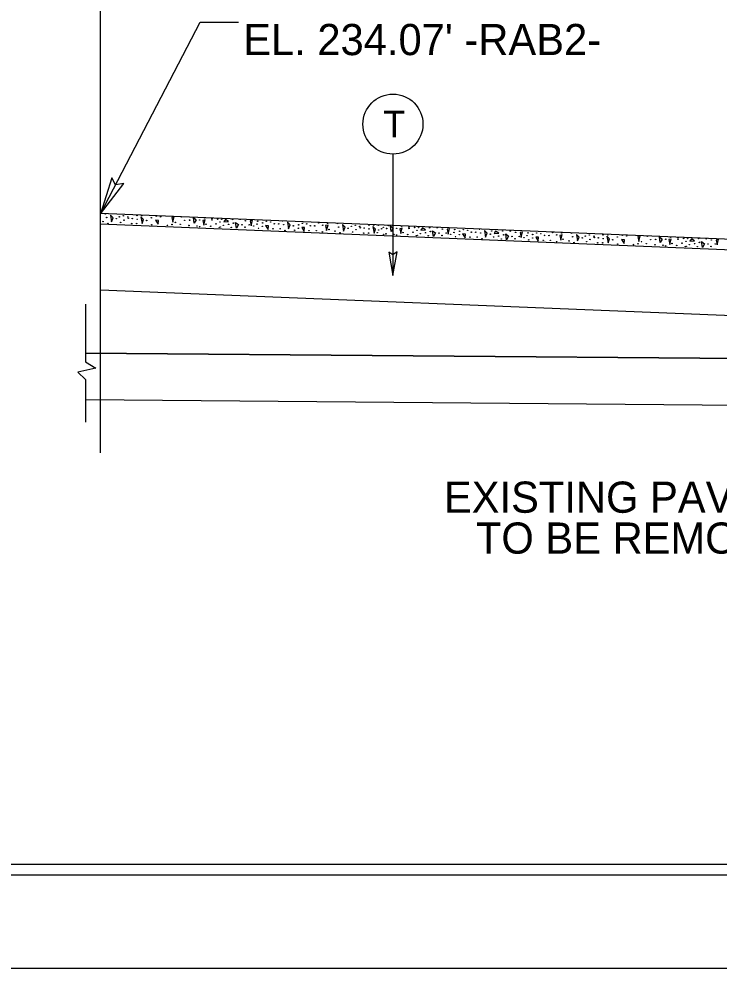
# Model space of a CAD drawing. Extents: x 573748 to 574632, y -54663 to -53209.
# Drawn here: x 574026.74 to 574060.43, y -54603.65 to -54558 of the extents above; entities that cross this region are included whole.
import ezdxf

# ---------------------------------------------------------------- set-up
doc = ezdxf.new("R2010")
doc.units = 0
for name, color, linetype in [('Prop Dimension', 7, 'Continuous'), ('Prop Dimension Text', 7, 'Continuous'), ('Prop Rem of Exist Asph Pvmt', 7, 'Continuous'), ('Prop Terminator CELL', 7, 'Continuous'), ('Sheet Cutting Line CELL', 7, 'Continuous'), ('Sheet Plot Border Inside CELL', 7, 'Continuous'), ('Sheet Plot Border Outside CELL', 7, 'Continuous'), ('Sheet Typical CELL', 7, 'Continuous'), ('Typical Curb CELL', 7, 'Continuous'), ('Typical ID Circle CELL', 7, 'Continuous'), ('Typical Pavement Slope CELL', 7, 'Continuous'), ('Typical Terminator CELL', 7, 'Continuous'), ('Typical Text ID Circle CELL', 7, 'Continuous')]:
    doc.layers.add(name, color=color, linetype=linetype)

msp = doc.modelspace()

# ---------------------------------------------------------------- linework, layer by layer
at = {"layer": 'Prop Dimension'}
for p, q in [((574030.665, -54578.875), (574030.665, -54543.51)), ((574029.942, -54571.724), (574029.942, -54574.499)), ((574029.942, -54574.073), (574136.935, -54574.974)), ((574030.448, -54574.795), (574029.583, -54574.992)), ((574029.942, -54574.499), (574030.448, -54574.795)), ((574029.583, -54574.992), (574029.942, -54575.343)), ((574029.942, -54575.343), (574029.942, -54577.395)), ((574029.942, -54576.31), (574136.935, -54577.21))]:
    msp.add_line(p, q, dxfattribs=at)
msp.add_lwpolyline([(574030.665, -54567.379), (574035.456, -54558.159), (574037.312, -54558.159)], dxfattribs=at)
at = {"layer": 'Prop Rem of Exist Asph Pvmt'}
for p, q in [((574120.562, -54574.836), (574029.942, -54574.073)), ((574029.942, -54574.073), (574029.942, -54574.499)), ((574030.448, -54574.795), (574029.583, -54574.992)), ((574029.942, -54574.499), (574030.448, -54574.795)), ((574029.583, -54574.992), (574029.942, -54575.343)), ((574029.942, -54575.343), (574029.942, -54576.31)), ((574029.942, -54576.31), (574120.562, -54577.072))]:
    msp.add_line(p, q, dxfattribs=at)
at = {"layer": 'Prop Terminator CELL'}
msp.add_lwpolyline([(574031.22, -54565.638), (574030.665, -54567.379), (574031.784, -54565.92), (574031.394, -54565.977)], close=True, dxfattribs=at)
at = {"layer": 'Sheet Cutting Line CELL'}
msp.add_line((573944.171, -54603.647), (574280.971, -54603.647), dxfattribs=at)
at = {"layer": 'Sheet Plot Border Inside CELL'}
msp.add_lwpolyline([(574280.071, -54388.137), (573946.771, -54388.137), (573946.771, -54599.157), (574280.071, -54599.157)], close=True, dxfattribs=at)
at = {"layer": 'Sheet Plot Border Outside CELL'}
msp.add_lwpolyline([(574280.971, -54383.647), (573944.171, -54383.647), (573944.171, -54603.647), (574280.971, -54603.647)], close=True, dxfattribs=at)
at = {"layer": 'Sheet Typical CELL'}
msp.add_lwpolyline([(574277.571, -54388.647), (573977.571, -54388.647), (573977.571, -54598.647), (574277.571, -54598.647)], close=True, dxfattribs=at)
at = {"layer": 'Typical Curb CELL'}
for p, q in [((574031.146, -54567.434), (574031.201, -54567.75)), ((574031.273, -54567.561), (574031.146, -54567.434)), ((574031.201, -54567.75), (574031.273, -54567.561)), ((574032.615, -54567.522), (574032.669, -54567.836)), ((574032.741, -54567.649), (574032.615, -54567.522)), ((574034.212, -54567.517), (574034.096, -54567.542)), ((574034.096, -54567.542), (574034.146, -54567.772)), ((574034.146, -54567.772), (574034.212, -54567.517)), ((574035.136, -54567.552), (574035.276, -54567.661)), ((574035.177, -54567.828), (574035.136, -54567.552)), ((574032.669, -54567.836), (574032.741, -54567.649)), ((574033.451, -54567.691), (574033.313, -54567.685)), ((574033.313, -54567.685), (574033.436, -54567.871)), ((574033.436, -54567.871), (574033.451, -54567.691)), ((574035.276, -54567.661), (574035.177, -54567.828)), ((574035.699, -54567.663), (574035.583, -54567.687)), ((574035.583, -54567.687), (574035.633, -54567.918)), ((574035.633, -54567.918), (574035.699, -54567.663)), ((574036.677, -54567.642), (574036.606, -54567.76)), ((574036.606, -54567.76), (574036.827, -54567.742)), ((574036.827, -54567.742), (574036.677, -54567.642)), ((574037.166, -54567.782), (574037.306, -54567.891)), ((574037.206, -54568.058), (574037.166, -54567.782)), ((574037.306, -54567.891), (574037.206, -54568.058)), ((574037.979, -54567.689), (574037.862, -54567.713)), ((574037.862, -54567.713), (574037.912, -54567.944)), ((574037.912, -54567.944), (574037.979, -54567.689)), ((574038.748, -54567.942), (574038.611, -54567.936)), ((574038.611, -54567.936), (574038.734, -54568.122)), ((574038.734, -54568.122), (574038.748, -54567.942)), ((574039.665, -54567.778), (574039.719, -54568.094)), ((574039.791, -54567.906), (574039.665, -54567.778)), ((574039.719, -54568.094), (574039.791, -54567.906)), ((574041.614, -54567.915), (574041.497, -54567.939)), ((574041.497, -54567.939), (574041.547, -54568.17)), ((574041.547, -54568.17), (574041.614, -54567.915)), ((574042.306, -54567.893), (574042.361, -54568.209)), ((574042.433, -54568.02), (574042.306, -54567.893)), ((574042.361, -54568.209), (574042.433, -54568.02)), ((574043.774, -54567.981), (574043.829, -54568.295)), ((574043.901, -54568.108), (574043.774, -54567.981)), ((574044.614, -54567.953), (574044.754, -54568.063)), ((574044.655, -54568.229), (574044.614, -54567.953)), ((574040.483, -54568.034), (574040.346, -54568.029)), ((574040.346, -54568.029), (574040.469, -54568.215)), ((574040.469, -54568.215), (574040.483, -54568.034)), ((574043.829, -54568.295), (574043.901, -54568.108)), ((574044.754, -54568.063), (574044.655, -54568.229)), ((574045.177, -54568.064), (574045.061, -54568.089)), ((574045.061, -54568.089), (574045.111, -54568.319)), ((574045.111, -54568.319), (574045.177, -54568.064)), ((574046.155, -54568.043), (574046.084, -54568.161)), ((574046.084, -54568.161), (574046.306, -54568.144)), ((574046.306, -54568.144), (574046.155, -54568.043)), ((574046.644, -54568.183), (574046.784, -54568.292)), ((574046.684, -54568.459), (574046.644, -54568.183)), ((574046.784, -54568.292), (574046.684, -54568.459)), ((574047.457, -54568.09), (574047.34, -54568.115)), ((574047.34, -54568.115), (574047.39, -54568.345)), ((574047.39, -54568.345), (574047.457, -54568.09)), ((574048.226, -54568.343), (574048.089, -54568.338)), ((574048.089, -54568.338), (574048.212, -54568.523)), ((574048.212, -54568.523), (574048.226, -54568.343)), ((574049.143, -54568.179), (574049.197, -54568.495)), ((574049.269, -54568.307), (574049.143, -54568.179)), ((574049.197, -54568.495), (574049.269, -54568.307)), ((574049.674, -54568.202), (574049.603, -54568.32)), ((574049.603, -54568.32), (574049.825, -54568.302)), ((574049.825, -54568.302), (574049.674, -54568.202)), ((574050.163, -54568.342), (574050.303, -54568.451)), ((574050.204, -54568.618), (574050.163, -54568.342)), ((574050.303, -54568.451), (574050.204, -54568.618)), ((574050.976, -54568.249), (574050.859, -54568.273)), ((574050.859, -54568.273), (574050.909, -54568.504)), ((574050.909, -54568.504), (574050.976, -54568.249)), ((574052.876, -54568.382), (574052.759, -54568.407)), ((574052.759, -54568.407), (574052.809, -54568.637)), ((574052.809, -54568.637), (574052.876, -54568.382)), ((574053.568, -54568.36), (574053.623, -54568.676)), ((574053.695, -54568.487), (574053.568, -54568.36)), ((574055.036, -54568.448), (574055.091, -54568.762)), ((574055.163, -54568.576), (574055.036, -54568.448)), ((574056.634, -54568.443), (574056.517, -54568.468)), ((574056.517, -54568.468), (574056.567, -54568.699)), ((574056.567, -54568.699), (574056.634, -54568.443)), ((574057.558, -54568.479), (574057.698, -54568.588)), ((574057.598, -54568.755), (574057.558, -54568.479)), ((574051.746, -54568.502), (574051.608, -54568.496)), ((574051.608, -54568.496), (574051.731, -54568.682)), ((574051.731, -54568.682), (574051.746, -54568.502)), ((574053.623, -54568.676), (574053.695, -54568.487)), ((574055.091, -54568.762), (574055.163, -54568.576)), ((574055.872, -54568.617), (574055.735, -54568.612)), ((574055.735, -54568.612), (574055.858, -54568.797)), ((574055.858, -54568.797), (574055.872, -54568.617)), ((574057.698, -54568.588), (574057.598, -54568.755)), ((574058.121, -54568.589), (574058.004, -54568.614)), ((574058.004, -54568.614), (574058.054, -54568.844)), ((574058.054, -54568.844), (574058.121, -54568.589)), ((574059.099, -54568.569), (574059.027, -54568.686)), ((574059.027, -54568.686), (574059.249, -54568.669)), ((574059.249, -54568.669), (574059.099, -54568.569)), ((574059.588, -54568.708), (574059.728, -54568.817)), ((574059.628, -54568.984), (574059.588, -54568.708)), ((574059.728, -54568.817), (574059.628, -54568.984)), ((574060.4, -54568.615), (574060.284, -54568.64)), ((574060.284, -54568.64), (574060.334, -54568.87)), ((574060.334, -54568.87), (574060.4, -54568.615))]:
    msp.add_line(p, q, dxfattribs=at)
for centre in [(574030.904, -54567.374), (574030.962, -54567.55), (574031.571, -54567.516), (574031.768, -54567.466), (574031.983, -54567.522), (574032.422, -54567.457), (574032.654, -54567.456), (574033.116, -54567.563), (574033.352, -54567.482), (574033.558, -54567.514), (574034.559, -54567.521), (574035.675, -54567.574), (574030.793, -54567.745), (574031.024, -54567.827), (574031.423, -54567.605), (574031.634, -54567.786), (574031.796, -54567.676), (574032.006, -54567.584), (574032.171, -54567.842), (574032.193, -54567.6), (574032.403, -54567.841), (574032.43, -54567.638), (574032.891, -54567.693), (574033.131, -54567.9), (574033.89, -54567.926), (574034.108, -54567.886), (574034.274, -54567.786), (574034.502, -54567.88), (574034.716, -54567.688), (574034.919, -54567.933), (574034.951, -54567.678), (574035.309, -54567.958), (574035.431, -54567.991), (574035.443, -54567.668), (574035.742, -54567.874), (574035.97, -54567.968), (574036.027, -54567.609), (574036.035, -54567.672), (574036.22, -54567.858), (574036.297, -54567.629), (574036.388, -54568.021), (574036.419, -54567.766), (574036.433, -54568.007), (574036.497, -54567.638), (574036.579, -54567.928), (574036.826, -54567.883), (574036.956, -54568.025), (574037.021, -54567.641), (574037.063, -54567.823), (574037.388, -54567.643), (574037.473, -54567.898), (574037.618, -54568.013), (574037.638, -54567.706), (574037.819, -54567.899), (574038.04, -54567.958), (574038.192, -54567.865), (574038.234, -54567.728), (574038.457, -54567.973), (574038.464, -54567.808), (574038.65, -54567.733), (574038.856, -54567.765), (574039.031, -54567.852), (574039.243, -54567.857), (574039.423, -54567.718), (574039.48, -54567.894), (574039.941, -54567.95), (574040.199, -54567.901), (574040.385, -54567.825), (574040.591, -54567.858), (574040.766, -54567.945), (574040.978, -54567.95), (574041.158, -54567.811), (574041.357, -54567.92), (574041.59, -54567.826), (574042.064, -54567.833), (574042.122, -54568.009), (574042.73, -54567.975), (574042.928, -54567.925), (574043.143, -54567.981), (574043.582, -54567.916), (574043.813, -54567.915), (574044.037, -54567.923), (574044.276, -54568.022), (574044.512, -54567.941), (574045.153, -54567.975), (574045.505, -54568.01), (574045.775, -54568.031), (574045.975, -54568.039), (574038.269, -54568.068), (574038.969, -54568.09), (574039.311, -54568.089), (574039.542, -54568.172), (574040.004, -54568.161), (574040.192, -54568.066), (574040.704, -54568.183), (574041.046, -54568.182), (574041.345, -54568.243), (574041.657, -54568.126), (574041.952, -54568.204), (574042.184, -54568.287), (574042.582, -54568.064), (574042.793, -54568.246), (574042.956, -54568.135), (574043.165, -54568.043), (574043.331, -54568.301), (574043.353, -54568.06), (574043.562, -54568.301), (574043.59, -54568.097), (574043.98, -54568.281), (574044.051, -54568.152), (574044.194, -54568.089), (574044.29, -54568.359), (574044.397, -54568.335), (574044.429, -54568.079), (574044.787, -54568.359), (574044.909, -54568.392), (574044.921, -54568.07), (574045.221, -54568.275), (574045.448, -54568.369), (574045.513, -54568.073), (574045.698, -54568.259), (574045.866, -54568.422), (574045.897, -54568.167), (574045.911, -54568.409), (574046.057, -54568.329), (574046.304, -54568.284), (574046.434, -54568.427), (574046.499, -54568.042), (574046.541, -54568.224), (574046.866, -54568.044), (574046.951, -54568.299), (574047.096, -54568.414), (574047.116, -54568.107), (574047.297, -54568.3), (574047.519, -54568.359), (574047.67, -54568.267), (574047.712, -54568.129), (574047.747, -54568.469), (574047.935, -54568.375), (574047.942, -54568.209), (574048.128, -54568.134), (574048.334, -54568.167), (574048.447, -54568.491), (574048.509, -54568.254), (574048.721, -54568.258), (574048.789, -54568.491), (574048.901, -54568.119), (574048.958, -54568.296), (574049.419, -54568.351), (574049.494, -54568.198), (574049.576, -54568.488), (574049.823, -54568.443), (574050.018, -54568.201), (574050.061, -54568.383), (574050.385, -54568.203), (574050.47, -54568.458), (574050.635, -54568.266), (574050.816, -54568.459), (574051.189, -54568.425), (574051.232, -54568.288), (574051.461, -54568.368), (574051.647, -54568.293), (574051.853, -54568.325), (574052.028, -54568.412), (574052.24, -54568.417), (574052.42, -54568.278), (574052.62, -54568.387), (574052.852, -54568.293), (574053.326, -54568.3), (574053.384, -54568.476), (574053.993, -54568.442), (574054.19, -54568.393), (574054.405, -54568.448), (574054.844, -54568.383), (574055.076, -54568.382), (574055.538, -54568.489), (574055.774, -54568.408), (574055.98, -54568.441), (574056.981, -54568.448), (574049.021, -54568.573), (574049.953, -54568.585), (574050.615, -54568.573), (574051.038, -54568.518), (574051.267, -54568.628), (574051.454, -54568.533), (574051.966, -54568.65), (574052.309, -54568.649), (574052.608, -54568.71), (574052.919, -54568.593), (574053.215, -54568.671), (574053.446, -54568.754), (574053.845, -54568.532), (574054.056, -54568.713), (574054.218, -54568.603), (574054.428, -54568.51), (574054.593, -54568.768), (574054.615, -54568.527), (574054.825, -54568.768), (574054.852, -54568.564), (574055.313, -54568.619), (574055.553, -54568.826), (574056.312, -54568.852), (574056.53, -54568.812), (574056.696, -54568.713), (574056.924, -54568.806), (574057.138, -54568.614), (574057.341, -54568.86), (574057.373, -54568.605), (574057.731, -54568.884), (574057.853, -54568.917), (574057.865, -54568.595), (574058.097, -54568.5), (574058.164, -54568.8), (574058.392, -54568.894), (574058.449, -54568.536), (574058.457, -54568.598), (574058.641, -54568.784), (574058.719, -54568.556), (574058.81, -54568.948), (574058.841, -54568.693), (574058.854, -54568.934), (574058.918, -54568.565), (574059.001, -54568.854), (574059.248, -54568.809), (574059.378, -54568.952), (574059.443, -54568.567), (574059.485, -54568.749), (574059.81, -54568.57), (574059.895, -54568.824), (574060.039, -54568.939), (574060.059, -54568.632), (574060.241, -54568.826)]:
    msp.add_ellipse(centre, major_axis=(0.0005, 0.0133), ratio=0.761905, dxfattribs=at)
at = {"layer": 'Typical ID Circle CELL'}
msp.add_line((574044.738, -54564.501), (574044.738, -54570.335), dxfattribs=at)
msp.add_circle((574044.738, -54563.058), 1.443, dxfattribs=at)
at = {"layer": 'Typical Pavement Slope CELL'}
for p, q in [((574030.668, -54567.336), (574103.469, -54570.338)), ((574030.665, -54567.85), (574103.469, -54570.852)), ((574030.665, -54571.026), (574120.562, -54574.704))]:
    msp.add_line(p, q, dxfattribs=at)
at = {"layer": 'Typical Terminator CELL'}
msp.add_lwpolyline([(574044.544, -54569.21), (574044.738, -54570.335), (574044.938, -54569.203), (574044.738, -54569.347)], close=True, dxfattribs=at)

# ---------------------------------------------------------------- texts
at = {"layer": 'Prop Dimension'}
for s, p in [('EXISTING PAVEMENT', (574047.188, -54581.75)), ('TO BE REMOVED', (574048.729, -54583.717))]:
    msp.add_text(s, height=1.5, rotation=360, dxfattribs=at).set_placement(p)
at = {"layer": 'Prop Dimension Text'}
msp.add_text("EL. 234.07' -RAB2-", height=1.5, dxfattribs=at).set_placement((574037.533, -54559.74))
at = {"layer": 'Typical Text ID Circle CELL'}
msp.add_text('T', height=1.291, dxfattribs=at).set_placement((574044.272, -54563.701))

doc.saveas('drawing.dxf')
